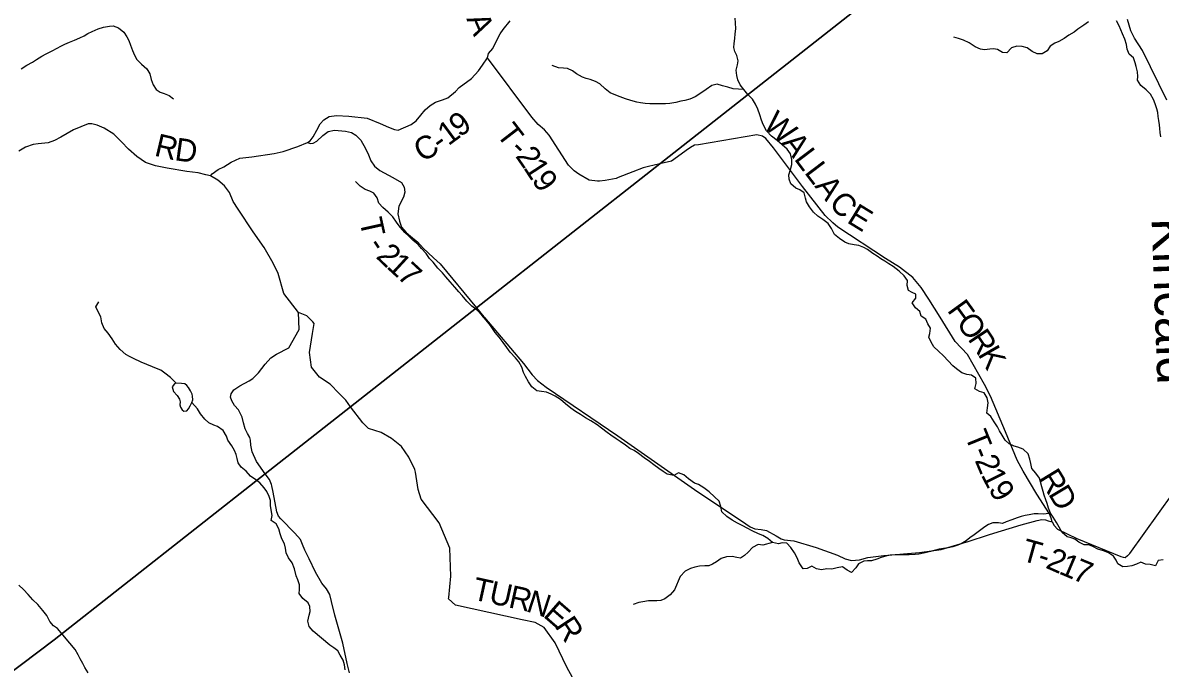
# Model space of a CAD drawing. Extents: x 1578669 to 1989827, y 208020 to 553079.
# Drawn here: x 1731603 to 1746556, y 410463 to 418953 of the extents above; entities that cross this region are included whole.
import ezdxf

# ---------------------------------------------------------------- set-up
doc = ezdxf.new("R2010")
doc.units = 0
for name, color, linetype in [('GM_X_County_Road', 7, 'Continuous'), ('GM_X_County_Road_Text', 7, 'Continuous'), ('GM_X_Minor_Lake', 7, 'Continuous'), ('GM_X_Minor_River', 7, 'Continuous'), ('GM_X_Minor_River_Text', 7, 'Continuous'), ('GM_X_Township', 7, 'Continuous'), ('GM_X_Township_Road', 7, 'Continuous'), ('GM_X_Township_Road_Text', 7, 'Continuous'), ('GM_X_Township_ROW', 7, 'Continuous')]:
    doc.layers.add(name, color=color, linetype=linetype)

msp = doc.modelspace()

# ---------------------------------------------------------------- linework, layer by layer
at = {"layer": 'GM_X_County_Road'}
for points in [[(1746641, 417936), (1746325, 418588), (1746218, 418749), (1746171, 418846), (1746126, 418997)], [(1734072, 416939), (1734091, 416964), (1734170, 417024), (1734246, 417059), (1734345, 417121), (1734456, 417170), (1734613, 417189), (1734906, 417235), (1735026, 417260), (1735219, 417323), (1735346, 417376), (1735383, 417400), (1735420, 417450), (1735470, 417540), (1735512, 417621), (1735561, 417677), (1735633, 417718), (1735728, 417731), (1735890, 417726), (1736131, 417697), (1736300, 417628), (1736412, 417581), (1736489, 417547), (1736539, 417539), (1736711, 417615), (1736773, 417661), (1736835, 417736), (1736892, 417806), (1736961, 417863), (1737031, 417906), (1737121, 417940), (1737189, 417967), (1737293, 418050), (1737341, 418100), (1737501, 418219), (1737596, 418319), (1737648, 418393), (1737711, 418493), (1737725, 418546), (1737781, 418614), (1737823, 418696), (1737880, 418806), (1737919, 418863), (1738009, 418978)], [(1734894, 412778), (1734877, 412864), (1734872, 412879), (1734847, 412944), (1734791, 413021), (1734676, 413183), (1734620, 413308), (1734602, 413395), (1734595, 413464), (1734589, 413500), (1734557, 413552), (1734526, 413610), (1734507, 413689), (1734489, 413766), (1734439, 413861), (1734388, 413921), (1734351, 413979), (1734333, 414030), (1734345, 414074), (1734379, 414123), (1734456, 414179), (1734580, 414244), (1734629, 414276), (1734703, 414349), (1734789, 414463), (1734863, 414546), (1734937, 414593), (1735099, 414678), (1735235, 414918), (1735228, 415143), (1735037, 415393), (1734960, 415656), (1734894, 415790), (1734777, 415998), (1734633, 416204), (1734434, 416500), (1734369, 416601), (1734320, 416722), (1734256, 416808), (1734168, 416884), (1734072, 416939), (1734012, 416951), (1733911, 416978), (1733762, 416995), (1733503, 417039), (1733348, 417069), (1733218, 417115), (1733101, 417193), (1732994, 417290), (1732902, 417387), (1732799, 417486), (1732674, 417566), (1732582, 417607), (1732510, 417623), (1732463, 417623), (1732272, 417545), (1732103, 417448), (1732021, 417402), (1731937, 417375), (1731808, 417361), (1731742, 417350), (1731640, 417315), (1731553, 417263)], [(1735897, 410403), (1735869, 410528), (1735810, 410794), (1735707, 411163), (1735661, 411340), (1735638, 411435), (1735597, 411509), (1735536, 411584), (1735451, 411729), (1735369, 411903), (1735310, 412015), (1735282, 412092), (1735255, 412158), (1735178, 412238), (1734995, 412429), (1734964, 412462), (1734943, 412520), (1734894, 412778)]]:
    msp.add_lwpolyline(points, dxfattribs=at)
at = {"layer": 'GM_X_Minor_Lake'}
for points in [[(1733620, 414214), (1733596, 414202), (1733566, 414164), (1733586, 414103), (1733632, 414049), (1733664, 414001), (1733672, 413965), (1733666, 413929), (1733676, 413895), (1733700, 413863), (1733722, 413843), (1733758, 413847), (1733782, 413875), (1733806, 413913), (1733828, 413957), (1733838, 413994), (1733836, 414040), (1733830, 414068), (1733810, 414110), (1733782, 414154), (1733758, 414184), (1733736, 414204), (1733688, 414208)], [(1733688, 414208), (1733620, 414214)]]:
    msp.add_lwpolyline(points, dxfattribs=at)
at = {"layer": 'GM_X_Minor_River'}
for points in [[(1743499, 414992), (1743475, 415056), (1743415, 415094), (1743395, 415156), (1743341, 415204), (1743295, 415268), (1743343, 415330), (1743345, 415381), (1743295, 415405), (1743245, 415433), (1743229, 415495), (1743235, 415561), (1743189, 415623), (1743123, 415685), (1743045, 415749), (1742988, 415783), (1742934, 415817), (1742884, 415847), (1742834, 415883), (1742776, 415919), (1742710, 415969), (1742660, 415997), (1742594, 416021), (1742532, 416033), (1742461, 416045), (1742411, 416065), (1742339, 416113), (1742273, 416169), (1742233, 416245), (1742191, 416313), (1742121, 416365), (1742057, 416409), (1742000, 416463), (1741944, 416532), (1741908, 416596), (1741892, 416646), (1741876, 416714), (1741818, 416756), (1741764, 416778), (1741698, 416834), (1741676, 416896), (1741674, 416952), (1741696, 417022), (1741714, 417089), (1741714, 417155), (1741694, 417227), (1741650, 417289), (1741586, 417347), (1741519, 417403), (1741447, 417463), (1741381, 417529), (1741335, 417614), (1741313, 417672), (1741291, 417742), (1741265, 417814), (1741235, 417882), (1741195, 417948), (1741135, 418010), (1741083, 418074), (1741036, 418136), (1741002, 418203), (1740988, 418259), (1740980, 418327), (1741000, 418397), (1741006, 418451), (1740988, 418521), (1740966, 418574), (1740950, 418628), (1740954, 418678), (1740964, 418746), (1740970, 418808), (1740976, 418874), (1740974, 418951), (1740968, 419011)], [(1731584, 418346), (1731658, 418394), (1731732, 418434), (1731782, 418469), (1731854, 418511), (1731912, 418545), (1731990, 418581), (1732055, 418617), (1732105, 418643), (1732157, 418670), (1732217, 418698), (1732285, 418724), (1732353, 418752), (1732409, 418780), (1732459, 418810), (1732517, 418837), (1732596, 418871), (1732666, 418895), (1732742, 418909), (1732792, 418911), (1732864, 418887), (1732930, 418829), (1732970, 418769), (1732996, 418717), (1733018, 418659), (1733047, 418589), (1733073, 418527), (1733103, 418467), (1733163, 418409), (1733233, 418346), (1733273, 418282), (1733293, 418208), (1733317, 418134), (1733355, 418076), (1733409, 418040), (1733461, 418020), (1733530, 417994), (1733584, 417954)], [(1745615, 418966), (1745551, 418921), (1745475, 418869), (1745423, 418829), (1745355, 418787), (1745295, 418747), (1745223, 418704), (1745170, 418686), (1745108, 418644), (1745068, 418582), (1745002, 418544), (1744938, 418542), (1744872, 418575), (1744806, 418622), (1744740, 418639), (1744671, 418645), (1744599, 418621), (1744541, 418557), (1744481, 418561), (1744415, 418599), (1744365, 418611), (1744315, 418605), (1744245, 418597), (1744195, 418603), (1744122, 418637), (1744044, 418687), (1743968, 418723), (1743906, 418744), (1743842, 418762)], [(1746551, 417561), (1746545, 417611), (1746537, 417668), (1746529, 417720), (1746523, 417770), (1746511, 417822), (1746491, 417886), (1746469, 417942), (1746429, 418014), (1746369, 418072), (1746303, 418128), (1746259, 418197), (1746263, 418247), (1746259, 418309), (1746240, 418377), (1746226, 418427), (1746206, 418491), (1746146, 418539), (1746120, 418603), (1746114, 418668), (1746090, 418738), (1746062, 418808), (1746040, 418860), (1746014, 418910), (1745982, 418976)], [(1741083, 418074), (1740940, 418084), (1740870, 418106), (1740802, 418124), (1740732, 418144), (1740662, 418128), (1740588, 418076), (1740517, 418027), (1740441, 417979), (1740371, 417947), (1740305, 417929), (1740255, 417919), (1740187, 417904), (1740109, 417890), (1740053, 417884), (1739978, 417884), (1739920, 417886), (1739848, 417888), (1739784, 417892), (1739726, 417898), (1739674, 417908), (1739598, 417928), (1739525, 417950), (1739455, 417980), (1739401, 417999), (1739327, 418031), (1739259, 418083), (1739189, 418150), (1739133, 418178), (1739061, 418208), (1739010, 418221), (1738960, 418235), (1738882, 418279), (1738830, 418319), (1738764, 418349), (1738710, 418355), (1738644, 418359), (1738562, 418391)], [(1746563, 417451), (1746555, 417511), (1746551, 417561)], [(1739001, 413755), (1738935, 413799), (1738868, 413839), (1738810, 413885), (1738740, 413941), (1738670, 413997), (1738600, 414043), (1738550, 414069), (1738490, 414093), (1738424, 414103), (1738363, 414113), (1738295, 414163), (1738253, 414229), (1738211, 414302), (1738185, 414354), (1738163, 414422), (1738125, 414494), (1738081, 414546), (1738009, 414620), (1737965, 414680), (1737918, 414746), (1737864, 414816), (1737814, 414880), (1737752, 414969), (1737696, 415039), (1737636, 415107), (1737580, 415167), (1737508, 415223), (1737441, 415293), (1737379, 415365), (1737335, 415415), (1737281, 415477), (1737221, 415545), (1737167, 415611), (1737121, 415663), (1737059, 415727), (1736997, 415802), (1736952, 415854), (1736906, 415916), (1736846, 415984), (1736800, 416036), (1736732, 416092), (1736680, 416144), (1736624, 416192), (1736564, 416262), (1736516, 416332), (1736467, 416398), (1736405, 416460), (1736337, 416522), (1736285, 416581), (1736263, 416649), (1736219, 416711), (1736165, 416739), (1736103, 416761), (1736039, 416805), (1735978, 416863)], [(1733620, 414214), (1733544, 414286), (1733472, 414344), (1733417, 414382), (1733363, 414406), (1733309, 414428), (1733235, 414458), (1733159, 414488), (1733059, 414536), (1733007, 414562), (1732957, 414590), (1732882, 414654), (1732822, 414726), (1732780, 414796), (1732726, 414872), (1732672, 414930), (1732644, 415006), (1732628, 415085), (1732602, 415135), (1732566, 415215), (1732604, 415283)], [(1746596, 411890), (1746530, 411882), (1746494, 411810), (1746425, 411826), (1746363, 411834), (1746299, 411859), (1746245, 411833), (1746181, 411811), (1746127, 411801), (1746063, 411797), (1745997, 411835), (1745975, 411885), (1745942, 411939), (1745878, 411983), (1745812, 412007), (1745734, 412031), (1745668, 412063), (1745616, 412085), (1745554, 412087), (1745484, 412121), (1745433, 412161), (1745383, 412179), (1745333, 412191), (1745265, 412249), (1745227, 412317), (1745191, 412379), (1745147, 412451), (1745113, 412503), (1745087, 412570), (1745069, 412628), (1745051, 412680), (1745031, 412738), (1745019, 412790), (1745001, 412848), (1744983, 412914), (1744968, 412964), (1744920, 413029), (1744870, 413089), (1744856, 413157), (1744844, 413213), (1744822, 413285), (1744754, 413343), (1744686, 413371), (1744636, 413385), (1744568, 413413), (1744518, 413461), (1744477, 413527), (1744443, 413587), (1744415, 413637), (1744375, 413704), (1744327, 413774), (1744277, 413820), (1744285, 413886), (1744293, 413954), (1744283, 414018), (1744243, 414084), (1744179, 414102), (1744121, 414138), (1744135, 414209), (1744133, 414277), (1744075, 414317), (1744013, 414327), (1743950, 414347), (1743880, 414403), (1743830, 414441), (1743768, 414505), (1743708, 414573), (1743642, 414633), (1743578, 414689), (1743544, 414753), (1743514, 414817), (1743526, 414867), (1743534, 414936), (1743499, 414992)], [(1735641, 410765), (1735420, 410950), (1735368, 411012), (1735352, 411084), (1735370, 411160), (1735380, 411210), (1735376, 411275), (1735354, 411325), (1735285, 411381), (1735237, 411447), (1735243, 411499), (1735241, 411559), (1735221, 411627), (1735199, 411679), (1735177, 411772), (1735145, 411850), (1735097, 411914), (1735067, 411980), (1735055, 412042), (1735045, 412100), (1735011, 412166), (1734987, 412233), (1734969, 412299), (1734933, 412363), (1734868, 412407), (1734883, 412473), (1734862, 412601), (1734862, 412668), (1734844, 412720), (1734810, 412786), (1734776, 412836), (1734718, 412904), (1734668, 412942), (1734596, 412990), (1734538, 413054), (1734476, 413106), (1734434, 413166), (1734422, 413220), (1734408, 413276), (1734385, 413329), (1734351, 413389), (1734301, 413461), (1734281, 413517), (1734237, 413591), (1734165, 413641), (1734115, 413661), (1734051, 413691), (1733995, 413741), (1733939, 413809), (1733900, 413873), (1733828, 413957)], [(1745113, 412503), (1745025, 412491), (1744952, 412495), (1744900, 412493), (1744832, 412483), (1744782, 412471), (1744726, 412457), (1744674, 412441), (1744604, 412416), (1744532, 412388), (1744482, 412368), (1744429, 412376), (1744357, 412374), (1744299, 412354), (1744249, 412322), (1744179, 412269), (1744111, 412217), (1744055, 412179), (1744005, 412141), (1743937, 412101), (1743884, 412076), (1743830, 412058), (1743768, 412046), (1743708, 412038), (1743652, 412030), (1743584, 412014), (1743534, 412000), (1743464, 411982), (1743383, 411965), (1743333, 411959), (1743257, 411957), (1743175, 411955), (1743123, 411957), (1743073, 411957), (1743005, 411951), (1742951, 411937), (1742887, 411921), (1742830, 411898), (1742760, 411876), (1742708, 411874), (1742658, 411870), (1742590, 411836), (1742554, 411784), (1742496, 411721), (1742442, 411755), (1742378, 411797), (1742311, 411783), (1742241, 411765), (1742173, 411771), (1742105, 411759), (1742039, 411773), (1741975, 411805), (1741913, 411775), (1741861, 411771), (1741808, 411849), (1741782, 411915), (1741748, 411981), (1741702, 412051), (1741646, 412109), (1741586, 412111), (1741536, 412099), (1741460, 412115), (1741398, 412169), (1741331, 412209), (1741275, 412233), (1741193, 412269), (1741125, 412307), (1741071, 412337), (1740997, 412373), (1740929, 412413), (1740857, 412461), (1740794, 412519), (1740778, 412591), (1740758, 412659), (1740698, 412719), (1740628, 412783), (1740556, 412837), (1740488, 412879), (1740434, 412899), (1740357, 412953), (1740293, 413005), (1740225, 413035), (1740161, 412999), (1740075, 413017), (1740021, 413051), (1739967, 413089), (1739899, 413139), (1739844, 413181), (1739770, 413231), (1739698, 413287), (1739640, 413325), (1739584, 413355), (1739528, 413397), (1739458, 413445), (1739406, 413481), (1739335, 413527), (1739285, 413563), (1739213, 413619), (1739153, 413665), (1739071, 413717), (1739001, 413755)], [(1741460, 412115), (1741331, 412081), (1741269, 412092), (1741197, 412050), (1741141, 411992), (1741091, 411948), (1741039, 411910), (1740989, 411920), (1740931, 411932), (1740855, 411929), (1740786, 411905), (1740724, 411865), (1740672, 411833), (1740620, 411811), (1740570, 411811), (1740498, 411806), (1740440, 411792), (1740380, 411776), (1740313, 411742), (1740247, 411672), (1740221, 411608), (1740199, 411557), (1740169, 411493), (1740115, 411427), (1740043, 411375), (1739991, 411356), (1739939, 411352), (1739877, 411350), (1739827, 411348), (1739756, 411338), (1739702, 411330), (1739628, 411302)], [(1732293, 410709), (1732059, 410987), (1732009, 411023), (1731961, 411079), (1731919, 411157), (1731865, 411225), (1731803, 411303), (1731734, 411365), (1731676, 411433), (1731614, 411501), (1731550, 411557)], [(1735840, 410441), (1735834, 410509), (1735816, 410569), (1735777, 410637), (1735743, 410691), (1735691, 410731), (1735641, 410765)], [(1732464, 410403), (1732420, 410475), (1732392, 410525), (1732357, 410589), (1732333, 410639), (1732293, 410709)]]:
    msp.add_lwpolyline(points, dxfattribs=at)
at = {"layer": 'GM_X_Township'}
for points in [[(1719425, 397707), (1720223, 401979), (1726373, 406560), (1726556, 406715), (1727692, 407573), (1728274, 408013), (1729470, 408917), (1732015, 410839), (1734791, 413021), (1735910, 413901), (1737568, 415203), (1739976, 417096), (1745267, 421255)], [(1745267, 421255), (1739976, 417096), (1737568, 415203), (1735910, 413901), (1734791, 413021), (1732015, 410839), (1729470, 408917), (1728274, 408013), (1727692, 407573), (1726556, 406715), (1726373, 406560), (1720223, 401979), (1721849, 410931), (1722260, 413009), (1723331, 419580)]]:
    msp.add_lwpolyline(points, dxfattribs=at)
at = {"layer": 'GM_X_Township_Road'}
for points in [[(1739182, 416871), (1739158, 416869), (1739050, 416884), (1738911, 416963), (1738851, 417006), (1738777, 417080), (1738523, 417473), (1738464, 417546), (1738377, 417616), (1738295, 417712), (1737711, 418493)], [(1735346, 417376), (1735385, 417364), (1735422, 417368), (1735469, 417396), (1735547, 417471), (1735619, 417521), (1735702, 417538), (1735848, 417527), (1735926, 417511), (1735982, 417472), (1736047, 417409), (1736110, 417300), (1736148, 417214), (1736179, 417138), (1736227, 417065), (1736299, 417010), (1736467, 416918), (1736580, 416852), (1736618, 416792), (1736628, 416725), (1736609, 416658), (1736548, 416542), (1736535, 416439), (1736556, 416341), (1736581, 416266), (1736643, 416194), (1736728, 416124), (1736794, 416071), (1736868, 415989), (1737002, 415860), (1737089, 415782), (1737568, 415203), (1737664, 415086), (1737665, 415086)], [(1745137, 412387), (1745123, 412436), (1745100, 412495), (1744934, 412754), (1744755, 413054), (1744676, 413198), (1744521, 413571), (1744325, 414042), (1744244, 414196), (1744022, 414590), (1743862, 414760), (1743662, 415081), (1743513, 415317), (1743412, 415472), (1743304, 415603), (1743128, 415740), (1742945, 415851), (1742317, 416266), (1742250, 416321), (1742152, 416416), (1741855, 416798), (1741472, 417308), (1741372, 417429), (1741327, 417461), (1741252, 417477), (1740488, 417349), (1740433, 417344), (1740382, 417314), (1740324, 417272), (1740323, 417272)], [(1740323, 417272), (1740162, 417156), (1740133, 417133), (1740035, 417109), (1740015, 417105), (1740014, 417105)], [(1736112, 413652), (1736072, 413691), (1735910, 413901), (1735851, 413987), (1735763, 414077), (1735645, 414198), (1735504, 414290), (1735397, 414425), (1735373, 414617), (1735414, 414867), (1735435, 414999), (1735416, 415019), (1735336, 415100), (1735228, 415143)], [(1738903, 410208), (1738757, 410476), (1738601, 410798), (1738457, 410998), (1738341, 411065), (1738170, 411102), (1737293, 411291), (1737202, 411375), (1737204, 411392), (1737230, 411675), (1737217, 412042), (1737078, 412377), (1736839, 412687), (1736799, 412812), (1736765, 413043), (1736759, 413079), (1736677, 413238), (1736581, 413381), (1736451, 413483), (1736314, 413562), (1736148, 413618), (1736112, 413652)], [(1746127, 411947), (1746128, 411948), (1746156, 411972), (1746722, 412761), (1746743, 412782), (1746786, 412790), (1747798, 412693)], [(1744015, 412127), (1744018, 412128), (1744311, 412223), (1744730, 412348), (1744937, 412408), (1744998, 412420), (1745048, 412417), (1745085, 412403), (1745137, 412387), (1745161, 412342), (1745206, 412291), (1745461, 412169), (1746039, 411931), (1746067, 411924), (1746097, 411920), (1746127, 411947)]]:
    msp.add_lwpolyline(points, dxfattribs=at)
at = {"layer": 'GM_X_Township_ROW'}
for points in [[(1740014, 417105), (1739976, 417096), (1739827, 417063), (1739757, 417044), (1739621, 416994), (1739432, 416917), (1739404, 416906), (1739260, 416876), (1739183, 416871), (1739182, 416871)], [(1737665, 415086), (1737671, 415078), (1738184, 414470), (1738301, 414322), (1738368, 414247), (1738482, 414159), (1739426, 413521), (1740478, 412785), (1741051, 412401), (1741164, 412323), (1741227, 412298), (1741308, 412288), (1741382, 412277), (1741509, 412203), (1741573, 412167), (1741613, 412154), (1741741, 412140), (1742033, 412052), (1742315, 411952), (1742415, 411903), (1742498, 411879), (1742603, 411891), (1742713, 411920), (1742924, 411946), (1743391, 411984), (1743676, 412027), (1744015, 412127)]]:
    msp.add_lwpolyline(points, dxfattribs=at)

# ---------------------------------------------------------------- texts
at = {"layer": 'GM_X_County_Road_Text'}
for s, rotation, p in [('1', 36.4405, (1737198, 417327)), ('9', 36.7325, (1737348, 417438)), ('R', 346.7409, (1733321, 417207)), ('D', 351.9325, (1733590, 417146)), ('C', 29.6892, (1736852, 417112)), ('-', 35.9832, (1737096, 417253))]:
    msp.add_text(s, height=300, rotation=rotation, dxfattribs=at).set_placement(p)
at = {"layer": 'GM_X_Minor_River_Text'}
msp.add_text('Kincaid', height=500.1, rotation=272.026, dxfattribs=at).set_placement((1746442, 416381))
at = {"layer": 'GM_X_Township_Road_Text'}
for s, rotation, p in [('A', 292.9567, (1737433, 419005)), ('W', 318.165, (1741324, 417592)), ('T', 307.5942, (1737818, 417487)), ('-', 317.2245, (1737992, 417268)), ('A', 307.4542, (1741573, 417371)), ('2', 304.8347, (1738072, 417198)), ('L', 307.1785, (1741734, 417161)), ('1', 303.1142, (1738176, 417048)), ('L', 307.1785, (1741869, 416983)), ('9', 305.6334, (1738285, 416881)), ('A', 307.2716, (1742005, 416803)), ('C', 313.2154, (1742187, 416567)), ('E', 328.4969, (1742423, 416333)), ('T', 282.5674, (1736026, 416354)), ('-', 303.6735, (1736122, 416025)), ('2', 316.0847, (1736236, 415868)), ('1', 317.2467, (1736374, 415736)), ('7', 317.1641, (1736509, 415610)), ('F', 305.9138, (1743747, 415170)), ('O', 305.793, (1743865, 415006)), ('R', 303.8016, (1744018, 414794)), ('K', 299.8985, (1744152, 414594)), ('T', 292.1564, (1743981, 413523)), ('-', 292.2789, (1744066, 413315)), ('2', 292.798, (1744114, 413198)), ('1', 296.747, (1744195, 413007)), ('R', 301.4986, (1744948, 412967)), ('9', 301.0657, (1744290, 412820)), ('D', 300.9288, (1745077, 412757)), ('T', 344.3701, (1744714, 411884)), ('2', 336.1707, (1745036, 411789)), ('-', 342.0094, (1744927, 411825)), ('1', 336.9786, (1745210, 411713)), ('7', 337.7136, (1745384, 411639)), ('T', 347.6873, (1737499, 411371)), ('U', 347.6842, (1737718, 411323)), ('R', 347.5495, (1737976, 411266)), ('N', 342.0938, (1738209, 411215)), ('E', 318.9487, (1738432, 411150)), ('R', 303.4043, (1738588, 411019))]:
    msp.add_text(s, height=300, rotation=rotation, dxfattribs=at).set_placement(p)

doc.saveas('drawing.dxf')
